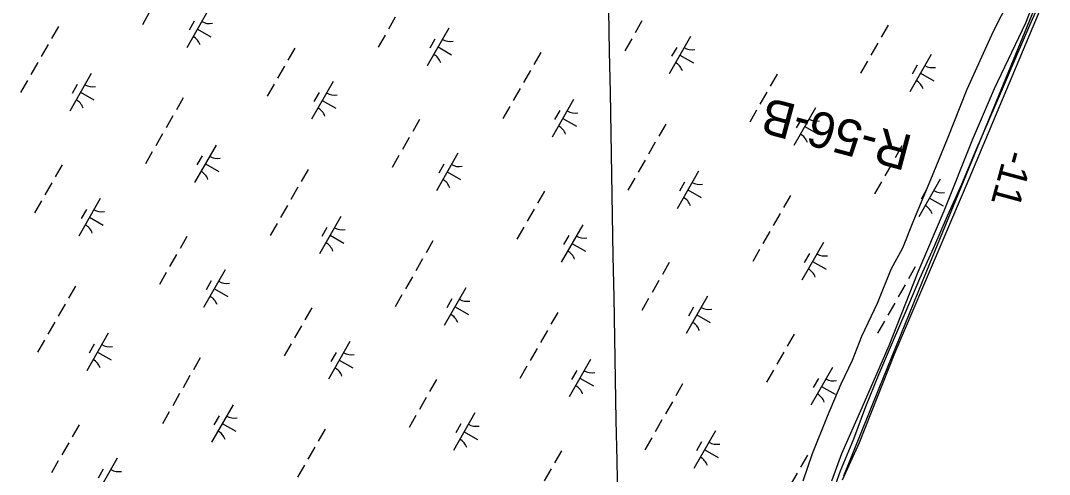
# Model space of a CAD drawing. Extents: x 3930721 to 3950824, y 220441 to 242861.
# Drawn here: x 3940000 to 3941189, y 233943 to 234468 of the extents above; entities that cross this region are included whole.
import ezdxf

# ---------------------------------------------------------------- set-up
doc = ezdxf.new("R2010")
doc.units = 0
for name, color, linetype in [('V-GRID-MAJR', 7, 'Continuous'), ('V-RIVR-EDGE', 7, 'Continuous'), ('V-RIVR-JETY', 7, 'Continuous'), ('V-RIVR-RANG', 7, 'Continuous'), ('V-RIVR-RANG-IDEN', 7, 'Continuous'), ('V-RRAP-FSHR', 7, 'Continuous'), ('V-WETL-SWMP', 7, 'Continuous')]:
    doc.layers.add(name, color=color, linetype=linetype)

msp = doc.modelspace()

# ---------------------------------------------------------------- linework, layer by layer
at = {"layer": 'V-GRID-MAJR'}
msp.add_spline([(3940914.4, 221486.3), (3940866.3, 224158.2), (3940756.9, 230218.1), (3940647.6, 236278.1), (3940604.7, 238656.8)], degree=3, dxfattribs=at)
at = {"layer": 'V-RIVR-EDGE'}
msp.add_lwpolyline([(3941743.2, 235978.5), (3941712.5, 235887.4), (3941694.1, 235799.3), (3941675.6, 235741), (3941639.8, 235638.6), (3941614.2, 235556.7), (3941561, 235412.4), (3941530.3, 235329.5), (3941431, 235072.5), (3941325.5, 234830.9), (3941271.3, 234707), (3941208.8, 234552.5), (3941096.2, 234284.2), (3941010.2, 234082.6), (3940969.3, 233979.2), (3940949.8, 233936.2)], dxfattribs=at)
at = {"layer": 'V-RIVR-JETY'}
for points in [[(3941390.3, 235013.1), (3941363.3, 234951.3), (3941338.2, 234892.2), (3941310.1, 234834.8), (3941287.9, 234779.2), (3941260, 234708.8), (3941225.7, 234626), (3941194.6, 234549), (3941161.8, 234464.6), (3941125.6, 234388.5), (3941100.2, 234329.1), (3941067.4, 234247), (3941037.2, 234176.7), (3941003.6, 234091.5), (3940972.6, 234019.6), (3940948.8, 233966.4), (3940937.5, 233934.9)], [(3940904.6, 233935.4), (3940915.6, 233966.9), (3940932.6, 234010), (3940948.7, 234047.3), (3940961.6, 234074.9), (3940972.5, 234102.5), (3940990.6, 234140.6), (3941006.4, 234180.2), (3941020, 234204.7), (3941032.5, 234236.9), (3941052.3, 234283.6), (3941071.7, 234330.6), (3941094.3, 234388.2), (3941124.9, 234455.4), (3941153, 234510.9), (3941172.7, 234550.9), (3941192.5, 234601)]]:
    msp.add_lwpolyline(points, dxfattribs=at)
at = {"layer": 'V-RRAP-FSHR'}
msp.add_lwpolyline([(3941197.9, 234535.3), (3941182.6, 234498.5), (3941166.3, 234461.8), (3941150.5, 234425.2), (3941134.7, 234388.3), (3941118.9, 234351.5), (3941103.1, 234314.8), (3941087.7, 234278.1), (3941071.1, 234241.4), (3941055.2, 234204.8), (3941039.2, 234168.7), (3941023.3, 234131.4), (3941007.4, 234094.7), (3940991.9, 234057.8), (3940976.9, 234020.7), (3940962.9, 233983.6), (3940947.6, 233946.3), (3940933.8, 233908.7)], dxfattribs=at)
at = {"layer": 'V-WETL-SWMP'}
for p, q in [((3941111.8, 234335.2), (3941182.7, 234507.5)), ((3940216.7, 234479.5), (3940191.9, 234436.1)), ((3940148.6, 234476.7), (3940140.7, 234462.8)), ((3940200.6, 234466.9), (3940194.6, 234456.5)), ((3940433.1, 234471.6), (3940425.2, 234457.7)), ((3940718.3, 234467.3), (3940710.3, 234453.4)), ((3940043.6, 234460.8), (3940035.6, 234446.9)), ((3940204.3, 234457.8), (3940219.9, 234448.9)), ((3940495, 234458.7), (3940470.1, 234415.4)), ((3941002.8, 234462.2), (3940994.8, 234448.3)), ((3940421.2, 234450.8), (3940413.2, 234436.9)), ((3940478.8, 234446.1), (3940472.9, 234435.7)), ((3940706.4, 234446.5), (3940698.4, 234432.6)), ((3940774.5, 234449.3), (3940749.6, 234405.9)), ((3940031.7, 234440), (3940023.7, 234426.1)), ((3940316.8, 234435.7), (3940308.9, 234421.8)), ((3940482.5, 234437.1), (3940498.2, 234428.1)), ((3940601.3, 234430.6), (3940593.4, 234416.7)), ((3940758.4, 234436.6), (3940752.4, 234426.2)), ((3940990.9, 234441.4), (3940982.9, 234427.5)), ((3940019.7, 234419.2), (3940011.8, 234405.3)), ((3940762.1, 234427.6), (3940777.7, 234418.7)), ((3940978.9, 234420.5), (3940971, 234406.7)), ((3941052.7, 234428.5), (3941027.8, 234385.1)), ((3940304.9, 234414.9), (3940296.9, 234401)), ((3940589.4, 234409.8), (3940581.4, 234395.9)), ((3941036.6, 234415.9), (3941030.6, 234405.5)), ((3941040.3, 234406.8), (3941055.9, 234397.9)), ((3940007.8, 234398.3), (3939999.8, 234384.4)), ((3940081.6, 234406.3), (3940056.7, 234362.9)), ((3940361.1, 234396.9), (3940336.2, 234353.5)), ((3940874.6, 234405.5), (3940866.6, 234391.6)), ((3940065.4, 234393.7), (3940059.5, 234383.2)), ((3940069.1, 234384.6), (3940084.7, 234375.7)), ((3940293, 234394), (3940285, 234380.2)), ((3940345, 234384.2), (3940339, 234373.8)), ((3940577.5, 234388.9), (3940569.5, 234375)), ((3940862.6, 234384.6), (3940854.7, 234370.8)), ((3940187.9, 234378.1), (3940180, 234364.3)), ((3940348.7, 234375.2), (3940364.3, 234366.2)), ((3940639.3, 234376.1), (3940614.4, 234332.7)), ((3940565.5, 234368.1), (3940557.6, 234354.2)), ((3940623.2, 234363.4), (3940617.2, 234353)), ((3940850.7, 234363.8), (3940842.8, 234349.9)), ((3940918.8, 234366.6), (3940894, 234323.2)), ((3940176, 234357.3), (3940168, 234343.4)), ((3940461.2, 234353), (3940453.2, 234339.1)), ((3940626.9, 234354.4), (3940642.5, 234345.4)), ((3940745.7, 234347.9), (3940737.7, 234334)), ((3940902.7, 234354), (3940896.7, 234343.6)), ((3940164.1, 234336.5), (3940156.1, 234322.6)), ((3940906.4, 234344.9), (3940922, 234336)), ((3941047.6, 234178.2), (3941111.8, 234335.2)), ((3940225.9, 234323.6), (3940201, 234280.3)), ((3940449.2, 234332.2), (3940441.3, 234318.3)), ((3940733.7, 234327.1), (3940725.8, 234313.2)), ((3940152.1, 234315.7), (3940144.2, 234301.8)), ((3940437.3, 234311.4), (3940429.4, 234297.5)), ((3940505.4, 234314.2), (3940480.6, 234270.8)), ((3941018.9, 234322.8), (3941011, 234308.9)), ((3940047.8, 234300.6), (3940039.8, 234286.7)), ((3940209.8, 234311), (3940203.8, 234300.6)), ((3940213.5, 234302), (3940229.1, 234293)), ((3940489.3, 234301.5), (3940483.3, 234291.1)), ((3940721.8, 234306.3), (3940713.9, 234292.4)), ((3941007, 234302), (3940999, 234288.1)), ((3940332.3, 234295.5), (3940324.3, 234281.6)), ((3940493, 234292.5), (3940508.6, 234283.6)), ((3940783.6, 234293.4), (3940758.8, 234250)), ((3940035.8, 234279.8), (3940027.9, 234265.9)), ((3940709.9, 234285.4), (3940701.9, 234271.6)), ((3940767.5, 234280.8), (3940761.5, 234270.4)), ((3940995.1, 234281.1), (3940987.1, 234267.3)), ((3941063.2, 234284), (3941038.3, 234240.6)), ((3940320.3, 234274.7), (3940312.4, 234260.8)), ((3940605.5, 234270.4), (3940597.6, 234256.5)), ((3940771.2, 234271.7), (3940786.8, 234262.8)), ((3940890, 234265.3), (3940882.1, 234251.4)), ((3941047, 234271.3), (3941041.1, 234260.9)), ((3940023.9, 234258.9), (3940016, 234245.1)), ((3940092, 234261.8), (3940067.2, 234218.4)), ((3940308.4, 234253.8), (3940300.5, 234239.9)), ((3941050.7, 234262.3), (3941066.4, 234253.3)), ((3940075.9, 234249.1), (3940069.9, 234238.7)), ((3940079.6, 234240.1), (3940095.2, 234231.1)), ((3940370.2, 234241), (3940345.4, 234197.6)), ((3940593.6, 234249.5), (3940585.6, 234235.7)), ((3940878.1, 234244.4), (3940870.1, 234230.5)), ((3940296.5, 234233), (3940288.5, 234219.1)), ((3940354.1, 234228.3), (3940348.1, 234217.9)), ((3940581.6, 234228.7), (3940573.7, 234214.8)), ((3940649.8, 234231.5), (3940624.9, 234188.1)), ((3940192.1, 234217.9), (3940184.2, 234204)), ((3940357.8, 234219.3), (3940373.4, 234210.3)), ((3940633.6, 234218.9), (3940627.7, 234208.5)), ((3940866.2, 234223.6), (3940858.2, 234209.7)), ((3940476.6, 234212.8), (3940468.7, 234198.9)), ((3940637.3, 234209.8), (3940653, 234200.9)), ((3940928, 234210.8), (3940903.1, 234167.4)), ((3940180.2, 234197.1), (3940172.2, 234183.2)), ((3940854.2, 234202.8), (3940846.3, 234188.9)), ((3940911.8, 234198.1), (3940905.9, 234187.7)), ((3940464.7, 234192), (3940456.7, 234178.1)), ((3940749.8, 234187.7), (3940741.9, 234173.8)), ((3940915.6, 234189.1), (3940931.2, 234180.1)), ((3941034.3, 234182.6), (3941026.4, 234168.7)), ((3940168.2, 234176.3), (3940160.3, 234162.4)), ((3940236.4, 234179.1), (3940211.5, 234135.7)), ((3940452.8, 234171.2), (3940444.8, 234157.3)), ((3940992.4, 234042.4), (3941047.6, 234178.2)), ((3940063.2, 234160.4), (3940055.3, 234146.5)), ((3940220.2, 234166.4), (3940214.3, 234156)), ((3940223.9, 234157.4), (3940239.6, 234148.5)), ((3940514.6, 234158.3), (3940489.7, 234114.9)), ((3940737.9, 234166.9), (3940730, 234153)), ((3941022.4, 234161.8), (3941014.5, 234147.9)), ((3940440.8, 234150.3), (3940432.9, 234136.5)), ((3940498.4, 234145.7), (3940492.5, 234135.2)), ((3940726, 234146), (3940718, 234132.2)), ((3940794.1, 234148.9), (3940769.3, 234105.5)), ((3940051.3, 234139.6), (3940043.3, 234125.7)), ((3940336.4, 234135.3), (3940328.5, 234121.4)), ((3940502.2, 234136.6), (3940517.8, 234127.7)), ((3940778, 234136.2), (3940772, 234125.8)), ((3941010.5, 234140.9), (3941002.5, 234127)), ((3940620.9, 234130.1), (3940613, 234116.3)), ((3940781.7, 234127.2), (3940797.3, 234118.2)), ((3940039.4, 234118.7), (3940031.4, 234104.8)), ((3940324.5, 234114.4), (3940316.6, 234100.6)), ((3940609, 234109.3), (3940601.1, 234095.4)), ((3940998.6, 234120.1), (3940990.6, 234106.2)), ((3940027.4, 234097.9), (3940019.5, 234084)), ((3940101.2, 234105.9), (3940076.3, 234062.5)), ((3940894.2, 234105), (3940886.2, 234091.1)), ((3940085, 234093.2), (3940079.1, 234082.8)), ((3940312.6, 234093.6), (3940304.6, 234079.7)), ((3940380.7, 234096.4), (3940355.9, 234053)), ((3940597.1, 234088.5), (3940589.1, 234074.6)), ((3940088.8, 234084.2), (3940104.4, 234075.2)), ((3940207.5, 234077.7), (3940199.6, 234063.8)), ((3940364.6, 234083.8), (3940358.6, 234073.4)), ((3940368.3, 234074.7), (3940383.9, 234065.8)), ((3940658.9, 234075.6), (3940634.1, 234032.3)), ((3940882.3, 234084.2), (3940874.3, 234070.3)), ((3940585.2, 234067.7), (3940577.2, 234053.8)), ((3940642.8, 234063), (3940636.8, 234052.6)), ((3940870.3, 234063.4), (3940862.4, 234049.5)), ((3940938.5, 234066.2), (3940913.6, 234022.8)), ((3940195.6, 234056.9), (3940187.7, 234043)), ((3940480.8, 234052.6), (3940472.8, 234038.7)), ((3940646.5, 234054), (3940662.1, 234045)), ((3940922.3, 234053.5), (3940916.4, 234043.1)), ((3940765.3, 234047.5), (3940757.3, 234033.6)), ((3940926, 234044.5), (3940941.6, 234035.6)), ((3940951.8, 233940.9), (3940992.4, 234042.4)), ((3940183.7, 234036.1), (3940175.7, 234022.2)), ((3940468.9, 234031.8), (3940460.9, 234017.9)), ((3940753.4, 234026.7), (3940745.4, 234012.8)), ((3940171.8, 234015.2), (3940163.8, 234001.3)), ((3940245.5, 234023.2), (3940220.7, 233979.8)), ((3940229.4, 234010.6), (3940223.4, 234000.1)), ((3940456.9, 234010.9), (3940449, 233997.1)), ((3940525.1, 234013.8), (3940500.2, 233970.4)), ((3940741.4, 234005.8), (3940733.5, 233991.9)), ((3940067.4, 234000.2), (3940059.4, 233986.3)), ((3940233.1, 234001.5), (3940248.7, 233992.6)), ((3940351.9, 233995), (3940343.9, 233981.2)), ((3940508.9, 234001.1), (3940503, 233990.7)), ((3940512.6, 233992.1), (3940528.2, 233983.1)), ((3940803.3, 233993), (3940778.4, 233949.6)), ((3940055.5, 233979.3), (3940047.5, 233965.5)), ((3940729.5, 233985), (3940721.6, 233971.1)), ((3940787.1, 233980.3), (3940781.2, 233969.9)), ((3940340, 233974.2), (3940332, 233960.3)), ((3940625.1, 233969.9), (3940617.2, 233956)), ((3940790.8, 233971.3), (3940806.5, 233962.3)), ((3940043.5, 233958.5), (3940035.6, 233944.6)), ((3940111.7, 233961.3), (3940086.8, 233917.9)), ((3940909.6, 233964.8), (3940901.7, 233950.9)), ((3940095.5, 233948.7), (3940089.5, 233938.3)), ((3940328, 233953.4), (3940320.1, 233939.5)), ((3940613.2, 233949.1), (3940605.2, 233935.2)), ((3940897.7, 233944), (3940889.8, 233930.1))]:
    msp.add_line(p, q, dxfattribs=at)
for centre, start, end in [((3940218.3, 234481.7), 239.4279, 280.9715), ((3940190.8, 234433.7), 19.4279, 60.9715), ((3940496.5, 234460.9), 239.4279, 280.9715), ((3940776, 234451.5), 239.4279, 280.9715), ((3940469, 234413), 19.4279, 60.9715), ((3940748.5, 234403.5), 19.4279, 60.9715), ((3941054.2, 234430.7), 239.4279, 280.9715), ((3941026.8, 234382.7), 19.4279, 60.9715), ((3940083.1, 234408.5), 239.4279, 280.9715), ((3940362.6, 234399), 239.4279, 280.9715), ((3940055.6, 234360.5), 19.4279, 60.9715), ((3940335.1, 234351.1), 19.4279, 60.9715), ((3940640.8, 234378.2), 239.4279, 280.9715), ((3940920.3, 234368.8), 239.4279, 280.9715), ((3940613.4, 234330.3), 19.4279, 60.9715), ((3940892.9, 234320.8), 19.4279, 60.9715), ((3940227.4, 234325.8), 239.4279, 280.9715), ((3940506.9, 234316.3), 239.4279, 280.9715), ((3940199.9, 234277.9), 19.4279, 60.9715), ((3940479.5, 234268.4), 19.4279, 60.9715), ((3940785.1, 234295.6), 239.4279, 280.9715), ((3941064.7, 234286.1), 239.4279, 280.9715), ((3940757.7, 234247.6), 19.4279, 60.9715), ((3941037.2, 234238.2), 19.4279, 60.9715), ((3940093.5, 234263.9), 239.4279, 280.9715), ((3940066.1, 234216), 19.4279, 60.9715), ((3940371.7, 234243.1), 239.4279, 280.9715), ((3940651.3, 234233.7), 239.4279, 280.9715), ((3940344.3, 234195.2), 19.4279, 60.9715), ((3940623.8, 234185.7), 19.4279, 60.9715), ((3940929.5, 234212.9), 239.4279, 280.9715), ((3940902, 234165), 19.4279, 60.9715), ((3940237.9, 234181.2), 239.4279, 280.9715), ((3940210.4, 234133.3), 19.4279, 60.9715), ((3940516.1, 234160.5), 239.4279, 280.9715), ((3940795.6, 234151), 239.4279, 280.9715), ((3940488.6, 234112.5), 19.4279, 60.9715), ((3940768.2, 234103.1), 19.4279, 60.9715), ((3940102.7, 234108), 239.4279, 280.9715), ((3940075.2, 234060.1), 19.4279, 60.9715), ((3940382.2, 234098.6), 239.4279, 280.9715), ((3940354.8, 234050.6), 19.4279, 60.9715), ((3940660.4, 234077.8), 239.4279, 280.9715), ((3940940, 234068.4), 239.4279, 280.9715), ((3940633, 234029.9), 19.4279, 60.9715), ((3940912.5, 234020.4), 19.4279, 60.9715), ((3940247, 234025.4), 239.4279, 280.9715), ((3940219.6, 233977.4), 19.4279, 60.9715), ((3940526.6, 234015.9), 239.4279, 280.9715), ((3940499.1, 233968), 19.4279, 60.9715), ((3940804.8, 233995.1), 239.4279, 280.9715), ((3940777.3, 233947.2), 19.4279, 60.9715), ((3940113.2, 233963.5), 239.4279, 280.9715)]:
    msp.add_arc(centre, 17.6, start, end, dxfattribs=at)

# ---------------------------------------------------------------- texts
at = {"layer": 'V-RIVR-RANG'}
msp.add_text('-11', height=33.5, rotation=254.9083, dxfattribs=at).set_placement((3941138.5, 234319.6))
at = {"layer": 'V-RIVR-RANG-IDEN'}
msp.add_text('R-56-B', height=41.5, rotation=165.0566, dxfattribs=at).set_placement((3941033, 234333.7))

doc.saveas('drawing.dxf')
